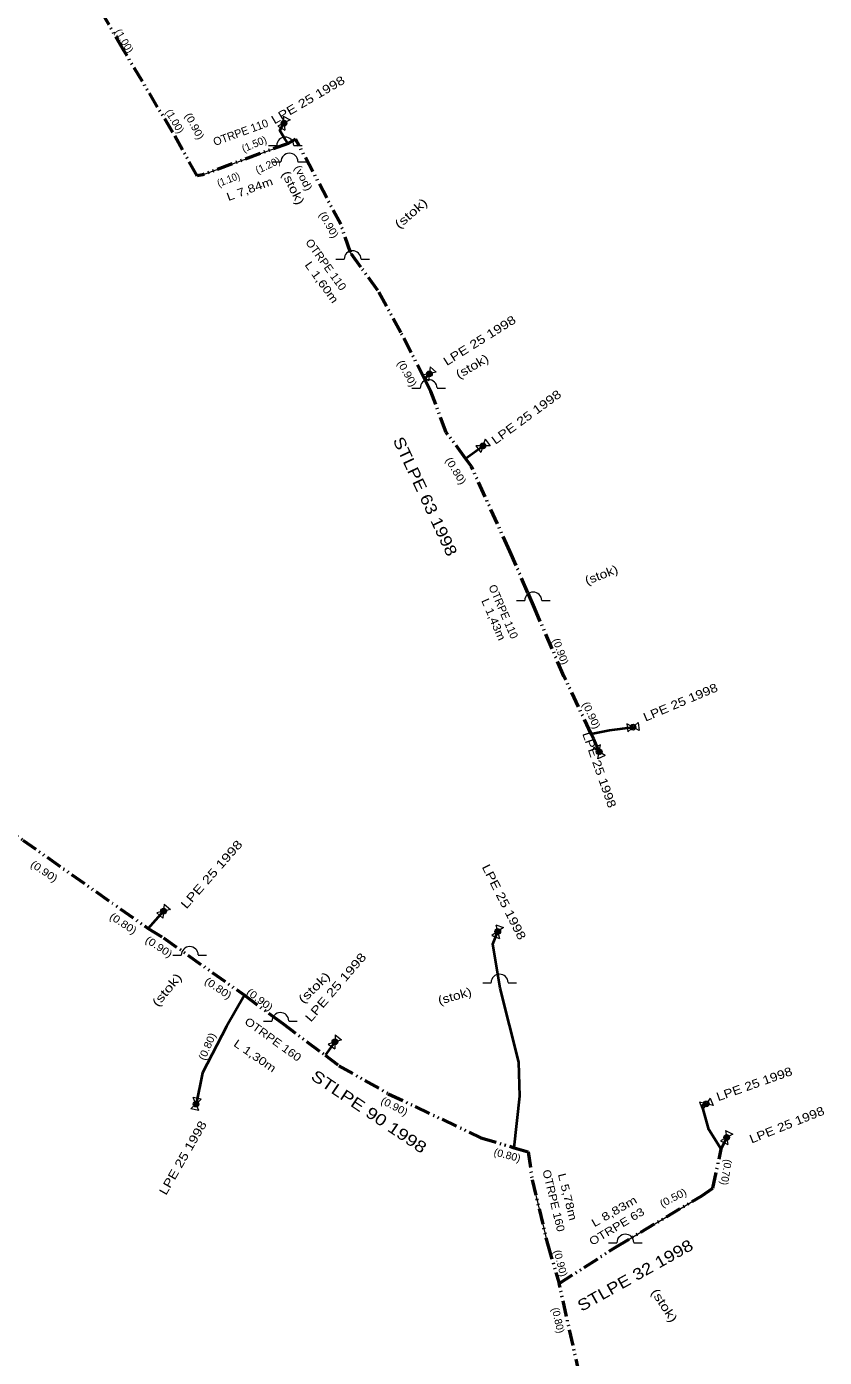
# Model space of a CAD drawing. Extents: x -648036 to -642998, y -1161549 to -1158141.
# Drawn here: x -644467.8 to -644398, y -1160146.5 to -1160030.1 of the extents above; entities that cross this region are included whole.
import ezdxf
from ezdxf.enums import TextEntityAlignment as Align

# ---------------------------------------------------------------- set-up
doc = ezdxf.new("R2010")
doc.units = 0
doc.header["$LTSCALE"] = 0.28
doc.linetypes.add('DASH_DOUBLE_DOT', pattern=[9.2, 5, -1.2, 0.3, -1.2, 0.3, -1.2])
for name, color, linetype, lineweight in [('12', 7, 'DASH_DOUBLE_DOT', 40), ('14', 7, 'Continuous', 13), ('15', 7, 'Continuous', 13), ('19', 7, 'Continuous', 13), ('8', 7, 'Continuous', 53)]:
    doc.layers.add(name, color=color, linetype=linetype, lineweight=lineweight)
for name, color, linetype in [('20', 7, 'Continuous'), ('22', 7, 'Continuous'), ('24', 7, 'Continuous'), ('27', 7, 'Continuous'), ('28', 7, 'Continuous')]:
    doc.layers.add(name, color=color, linetype=linetype)

msp = doc.modelspace()

# ---------------------------------------------------------------- linework, layer by layer
at = {"layer": '12', "linetype": 'Continuous'}
for p, q in [((-644432.96, -1160060.92), (-644432.54, -1160060.46)), ((-644429.38, -1160067.88), (-644427.85, -1160066.77)), ((-644418.19, -1160092.36), (-644417.68, -1160093.54)), ((-644457.15, -1160109), (-644455.81, -1160107.48)), ((-644407, -1160128.3), (-644406.52, -1160127.28))]:
    msp.add_line(p, q, dxfattribs=at)
at = {"layer": '12'}
msp.add_line((-644440.81, -1160118.92), (-644441.68, -1160120.08), dxfattribs=at)
at = {"layer": '12', "linetype": 'Continuous'}
for points in [[(-644444.91, -1160040.31), (-644445.2, -1160039.92), (-644445.62, -1160039.19), (-644445.27, -1160038.53)], [(-644418.38, -1160091.97), (-644416.79, -1160091.65), (-644414.72, -1160091.38)], [(-644425.13, -1160128.17), (-644424.62, -1160123.67), (-644424.72, -1160120.68), (-644426.34, -1160114.21), (-644426.98, -1160110.36), (-644426.56, -1160109.26)], [(-644448.73, -1160114.84), (-644450.31, -1160117.58), (-644452.4, -1160121.63), (-644452.97, -1160124.36)], [(-644407, -1160128.3), (-644408.08, -1160126.58), (-644408.67, -1160124.48), (-644408.31, -1160124.34)]]:
    msp.add_lwpolyline(points, dxfattribs=at)
at = {"layer": '14'}
for p, q in [((-644452.39, -1160043.05), (-644444.91, -1160040.31)), ((-644438.53, -1160051.14), (-644439.46, -1160049.85)), ((-644432.41, -1160062.02), (-644432.96, -1160060.92)), ((-644423.92, -1160079.62), (-644423.35, -1160080.93)), ((-644445.38, -1160117.31), (-644446.43, -1160116.54)), ((-644423.55, -1160130.97), (-644422.21, -1160136.59)), ((-644416.27, -1160136.89), (-644408.69, -1160132.37))]:
    msp.add_line(p, q, dxfattribs=at)
at = {"layer": '15'}
for p, q in [((-644444.719, -1160038.252), (-644445.82, -1160038.808)), ((-644445.82, -1160038.808), (-644445.192, -1160039.142)), ((-644445.348, -1160037.918), (-644445.192, -1160039.142)), ((-644445.348, -1160037.918), (-644444.719, -1160038.252)), ((-644446.635, -1160040.505), (-644445.9, -1160040.504)), ((-644444.414, -1160040.504), (-644443.68, -1160040.505)), ((-644446.275, -1160041.915), (-644445.54, -1160041.914)), ((-644444.054, -1160041.914), (-644443.32, -1160041.915)), ((-644440.735, -1160050.445), (-644440, -1160050.444)), ((-644438.514, -1160050.444), (-644437.78, -1160050.445)), ((-644431.937, -1160060.328), (-644433.142, -1160060.591)), ((-644433.142, -1160060.591), (-644432.617, -1160061.072)), ((-644432.463, -1160059.848), (-644432.617, -1160061.072)), ((-644432.463, -1160059.848), (-644431.937, -1160060.328)), ((-644434.085, -1160061.725), (-644433.35, -1160061.724)), ((-644431.864, -1160061.724), (-644431.13, -1160061.725)), ((-644427.233, -1160066.762), (-644428.466, -1160066.777)), ((-644428.466, -1160066.777), (-644428.049, -1160067.354)), ((-644427.651, -1160066.186), (-644428.049, -1160067.354)), ((-644427.651, -1160066.186), (-644427.233, -1160066.762)), ((-644424.925, -1160080.305), (-644424.19, -1160080.304)), ((-644422.704, -1160080.304), (-644421.97, -1160080.305)), ((-644415.265, -1160091.092), (-644415.174, -1160091.798)), ((-644414.174, -1160091.668), (-644415.265, -1160091.092)), ((-644414.266, -1160090.962), (-644415.174, -1160091.798)), ((-644414.266, -1160090.962), (-644414.174, -1160091.668)), ((-644417.553, -1160092.937), (-644418.207, -1160093.219)), ((-644417.153, -1160093.861), (-644418.207, -1160093.219)), ((-644417.807, -1160094.144), (-644417.553, -1160092.937)), ((-644417.153, -1160093.861), (-644417.807, -1160094.144)), ((-644455.21, -1160107.337), (-644456.41, -1160107.622)), ((-644455.744, -1160106.867), (-644455.876, -1160108.093)), ((-644455.744, -1160106.867), (-644455.21, -1160107.337)), ((-644456.41, -1160107.622), (-644455.876, -1160108.093)), ((-644426.713, -1160108.662), (-644426.407, -1160109.858)), ((-644426.713, -1160108.662), (-644426.048, -1160108.916)), ((-644426.048, -1160108.916), (-644427.072, -1160109.603)), ((-644427.072, -1160109.603), (-644426.407, -1160109.858)), ((-644454.995, -1160111.325), (-644454.26, -1160111.324)), ((-644452.774, -1160111.324), (-644452.04, -1160111.325)), ((-644427.875, -1160113.735), (-644427.14, -1160113.734)), ((-644425.654, -1160113.734), (-644424.92, -1160113.735)), ((-644447.065, -1160117.095), (-644446.33, -1160117.094)), ((-644444.844, -1160117.094), (-644444.11, -1160117.095)), ((-644440.223, -1160118.73), (-644441.397, -1160119.109)), ((-644441.397, -1160119.109), (-644440.828, -1160119.537)), ((-644440.792, -1160118.303), (-644440.828, -1160119.537)), ((-644440.792, -1160118.303), (-644440.223, -1160118.73)), ((-644452.519, -1160123.94), (-644453.215, -1160123.794)), ((-644452.725, -1160124.926), (-644453.215, -1160123.794)), ((-644407.969, -1160123.826), (-644408.651, -1160124.854)), ((-644407.969, -1160123.826), (-644407.711, -1160124.489)), ((-644453.421, -1160124.781), (-644452.519, -1160123.94)), ((-644452.725, -1160124.926), (-644453.421, -1160124.781)), ((-644408.908, -1160124.191), (-644408.651, -1160124.854)), ((-644407.711, -1160124.489), (-644408.908, -1160124.191)), ((-644405.983, -1160126.976), (-644407.056, -1160127.584)), ((-644406.628, -1160126.672), (-644406.412, -1160127.888)), ((-644406.628, -1160126.672), (-644405.983, -1160126.976)), ((-644407.056, -1160127.584), (-644406.412, -1160127.888)), ((-644416.865, -1160136.485), (-644416.13, -1160136.484)), ((-644414.644, -1160136.484), (-644413.91, -1160136.485))]:
    msp.add_line(p, q, dxfattribs=at)
for centre in [(-644445.1574, -1160040.5046), (-644444.7974, -1160041.9146), (-644439.2574, -1160050.4446), (-644432.6074, -1160061.7246), (-644423.4474, -1160080.3046), (-644453.5174, -1160111.3246), (-644426.3974, -1160113.7346), (-644445.5874, -1160117.0946), (-644415.3874, -1160136.4846)]:
    msp.add_arc(centre, 0.7431, 1.2748, 179.83951, dxfattribs=at)
at = {"layer": '19'}
for centre, radius in [((-644445.27, -1160038.53), 0.25), ((-644445.27, -1160038.53), 0.17), ((-644445.27, -1160038.53), 0.09), ((-644432.54, -1160060.46), 0.25), ((-644432.54, -1160060.46), 0.17), ((-644432.54, -1160060.46), 0.09), ((-644427.85, -1160066.77), 0.25), ((-644427.85, -1160066.77), 0.17), ((-644427.85, -1160066.77), 0.09), ((-644414.72, -1160091.38), 0.25), ((-644414.72, -1160091.38), 0.17), ((-644414.72, -1160091.38), 0.09), ((-644417.68, -1160093.54), 0.25), ((-644417.68, -1160093.54), 0.17), ((-644417.68, -1160093.54), 0.09), ((-644455.81, -1160107.48), 0.25), ((-644455.81, -1160107.48), 0.17), ((-644455.81, -1160107.48), 0.09), ((-644426.56, -1160109.26), 0.25), ((-644426.56, -1160109.26), 0.17), ((-644426.56, -1160109.26), 0.09), ((-644440.81, -1160118.92), 0.25), ((-644440.81, -1160118.92), 0.17), ((-644440.81, -1160118.92), 0.09), ((-644452.97, -1160124.36), 0.25), ((-644452.97, -1160124.36), 0.17), ((-644452.97, -1160124.36), 0.09), ((-644408.31, -1160124.34), 0.25), ((-644408.31, -1160124.34), 0.17), ((-644408.31, -1160124.34), 0.09), ((-644406.52, -1160127.28), 0.25), ((-644406.52, -1160127.28), 0.17), ((-644406.52, -1160127.28), 0.09)]:
    msp.add_circle(centre, radius, dxfattribs=at)
at = {"layer": '8', "linetype": 'DASH_DOUBLE_DOT'}
msp.add_line((-644418.19, -1160092.36), (-644418.38, -1160091.97), dxfattribs=at)
for points in [[(-644444.91, -1160040.31), (-644452.39, -1160043.05), (-644452.87, -1160043.14), (-644454.99, -1160039.37), (-644459.28, -1160032.19), (-644461.66, -1160028.08), (-644466.41, -1160020.66), (-644470.35, -1160015.08), (-644475.45, -1160009.38), (-644481.06, -1160003.99), (-644488.51, -1159997.16), (-644489.31, -1159996.42), (-644494.78, -1159991.67), (-644498.45, -1159989.02), (-644501.7, -1159985.93), (-644497.77, -1159979.7)], [(-644432.96, -1160060.92), (-644435.03, -1160056.85), (-644437.05, -1160053.17), (-644438.53, -1160051.14), (-644439.46, -1160049.85), (-644440.3, -1160047.39), (-644443.93, -1160040.53), (-644444.25, -1160039.95), (-644444.91, -1160040.31)], [(-644429.38, -1160067.88), (-644431.07, -1160065.59), (-644432.41, -1160062.02), (-644432.96, -1160060.92)], [(-644418.38, -1160091.97), (-644420.76, -1160086.91), (-644423.35, -1160080.93), (-644423.92, -1160079.62), (-644425.5, -1160075.98), (-644428.85, -1160068.59), (-644429.38, -1160067.88)], [(-644480.31, -1160092.29), (-644469.71, -1160100.17), (-644468.14, -1160101.26), (-644457.15, -1160109)], [(-644457.15, -1160109), (-644455.81, -1160109.81), (-644448.73, -1160114.84)], [(-644448.73, -1160114.84), (-644446.43, -1160116.54), (-644445.38, -1160117.31), (-644441.68, -1160120.08)], [(-644441.68, -1160120.08), (-644440.46, -1160121), (-644436.14, -1160123.45), (-644428.04, -1160127.3), (-644425.13, -1160128.17)], [(-644425.13, -1160128.17), (-644423.91, -1160128.53), (-644423.55, -1160130.97)], [(-644421.18, -1160140.06), (-644416.27, -1160136.89), (-644408.69, -1160132.37), (-644407.73, -1160131.72), (-644407, -1160128.3)], [(-644423.55, -1160130.97), (-644422.21, -1160136.59), (-644421.18, -1160140.06)], [(-644418.17, -1160154.35), (-644418.83, -1160150.57), (-644421.18, -1160140.06)]]:
    msp.add_lwpolyline(points, dxfattribs=at)

# ---------------------------------------------------------------- texts
at = {"layer": '20'}
for s, rotation, width, p in [('STLPE 63 1998', 295.073, 1.2, (-644433.3625, -1160071.4031)), ('STLPE 90 1998', 326.013, 1.25, (-644438.108, -1160125.4279)), ('STLPE 32 1998', 29.221, 1.2, (-644414.2856, -1160139.7776))]:
    msp.add_text(s, height=1, rotation=rotation, dxfattribs=dict(at, width=width)).set_placement(p, align=Align.CENTER)
at = {"layer": '22'}
for rotation, width, p in [(30.367, 1.25, (-644442.9786, -1160036.8261)), (32.086, 1.25, (-644427.9537, -1160057.8701)), (36.096, 1.25, (-644423.8404, -1160064.552)), (22.918, 1.2, (-644410.42, -1160089.5489)), (289.344, 1.2, (-644418.0199, -1160095.2313)), (48.701, 1.3, (-644451.3278, -1160104.5065)), (296.792, 1.25, (-644426.3451, -1160106.841)), (49.274, 1.3, (-644440.4614, -1160114.3812)), (19.481, 1.2, (-644403.9786, -1160122.9496)), (21.772, 1.2, (-644401.1101, -1160126.52)), (60.161, 1.25, (-644453.7973, -1160129.2431))]:
    msp.add_text('LPE 25 1998', height=0.75, rotation=rotation, dxfattribs=dict(at, width=width)).set_placement(p, align=Align.CENTER)
at = {"layer": '24'}
for rotation, p in [(20.054, (-644448.943, -1160039.6753)), (293.354, (-644426.3832, -1160081.4103))]:
    msp.add_text('OTRPE 110', height=0.7, rotation=rotation, dxfattribs=at).set_placement(p, align=Align.CENTER)
for s, rotation, width, p in [('L 7,84m', 20.054, 1.25, (-644448.152, -1160044.6328)), ('OTRPE 110', 305.959, 1.05, (-644441.8723, -1160051.1165)), ('L 1,60m', 305.959, 1.25, (-644442.2525, -1160052.6595)), ('L 1,43m', 293.354, 1.15, (-644427.2439, -1160082.0923)), ('OTRPE 160', 324.294, 1.15, (-644446.4323, -1160118.9812)), ('L 1,30m', 325.44, 1.25, (-644448.0075, -1160120.42)), ('OTRPE 160', 283.614, 1.1, (-644421.9962, -1160132.8816)), ('L 5,78m', 284.187, 1.25, (-644420.7852, -1160132.5502)), ('L 8,83m', 29.794, 1.3, (-644416.1994, -1160134.0489)), ('OTRPE 63', 30.94, 1.2, (-644415.9664, -1160135.3628))]:
    msp.add_text(s, height=0.7, rotation=rotation, dxfattribs=dict(at, width=width)).set_placement(p, align=Align.CENTER)
at = {"layer": '27'}
for s, rotation, p in [('(1.00)', 300.803, (-644459.5355, -1160031.5136)), ('(1.00)', 300.803, (-644455.1055, -1160038.5336)), ('(1.50)', 22.918, (-644447.7551, -1160040.6631)), ('(1.20)', 25.21, (-644446.5494, -1160042.5185)), ('(0.70)', 260.696, (-644406.8788, -1160130.2695)), ('(0.80)', 283.041, (-644421.5906, -1160143.3452))]:
    msp.add_text(s, height=0.65, rotation=rotation, dxfattribs=at).set_placement(p, align=Align.CENTER)
for s, rotation, width, p in [('(0.90)', 298.511, 1.1, (-644453.3859, -1160038.9539)), ('(vod)', 296.792, 1.2, (-644443.8643, -1160043.4785)), ('(1.10)', 20.626, 0.9, (-644450.0215, -1160043.7618)), ('(0.90)', 299.657, 1.1, (-644441.62, -1160047.5897)), ('(0.90)', 299.657, 1.1, (-644434.77, -1160060.5897)), ('(0.80)', 301.376, 1.15, (-644430.4999, -1160069.1253)), ('(0.90)', 290.49, 1.05, (-644421.3646, -1160084.8657)), ('(0.90)', 295.073, 1.1, (-644418.6495, -1160090.4738)), ('(0.90)', 326.013, 1.15, (-644466.4452, -1160104.2537)), ('(0.80)', 326.586, 1.15, (-644459.523, -1160108.8209)), ('(0.90)', 326.586, 1.15, (-644456.398, -1160110.8602)), ('(0.80)', 325.44, 1.15, (-644451.2159, -1160114.4776)), ('(0.90)', 323.148, 1.15, (-644447.5789, -1160115.4732)), ('(0.80)', 66.463, 1.1, (-644451.6923, -1160119.4423)), ('(0.90)', 332.888, 1.1, (-644435.7541, -1160124.8386)), ('(0.80)', 345.494, 1.05, (-644425.8069, -1160129.1307)), ('(0.50)', 27.502, 1.1, (-644411.0576, -1160132.8384)), ('(0.90)', 284.76, 1.05, (-644421.3744, -1160138.3612))]:
    msp.add_text(s, height=0.65, rotation=rotation, dxfattribs=dict(at, width=width)).set_placement(p, align=Align.CENTER)
at = {"layer": '28'}
for rotation, width, p in [(296.219, 1.25, (-644444.8067, -1160044.3523)), (41.253, 1.35, (-644433.9078, -1160046.7105)), (30.367, 1.25, (-644428.6086, -1160060.1372)), (21.199, 1.2, (-644417.3531, -1160078.406)), (50.42, 1.35, (-644455.2327, -1160114.6009)), (44.118, 1.35, (-644442.3671, -1160114.4385)), (16.043, 1.2, (-644430.2206, -1160115.2618)), (303.095, 1.3, (-644412.2904, -1160142.1717))]:
    msp.add_text('(stok)', height=0.75, rotation=rotation, dxfattribs=dict(at, width=width)).set_placement(p, align=Align.CENTER)

doc.saveas('drawing.dxf')
